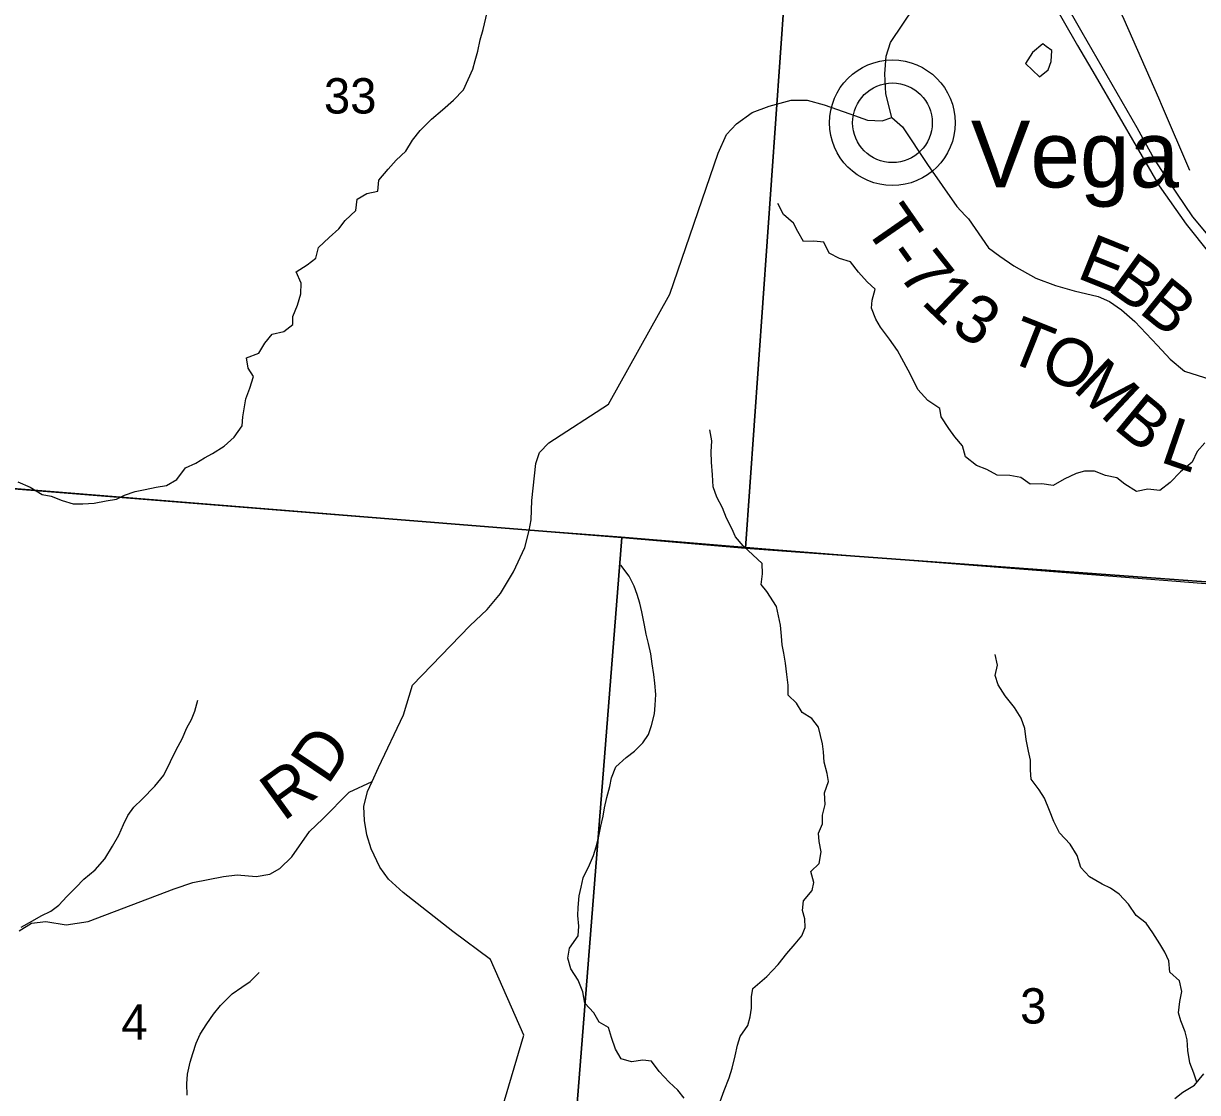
# Model space of a CAD drawing. Extents: x 0 to 42, y 0 to 22.
# Drawn here: x 6.349 to 7.044, y 16.803 to 17.436 of the extents above; entities that cross this region are included whole.
import ezdxf

# ---------------------------------------------------------------- set-up
doc = ezdxf.new("R2010")
doc.units = 0
for name, color, linetype in [('GM_X_Minor_Lake', 7, 'Continuous'), ('GM_X_Minor_River', 7, 'Continuous'), ('GM_X_Section', 7, 'Continuous'), ('GM_X_Section_Text', 7, 'Continuous'), ('GM_X_Township', 7, 'Continuous'), ('GM_X_Township_Road', 7, 'Continuous'), ('GM_X_Township_Road_Text', 7, 'Continuous'), ('GM_X_Unincorporated', 7, 'Continuous'), ('GM_X_Unincorporated_Location', 7, 'Continuous'), ('GM_X_Unincorporated_Text', 7, 'Continuous'), ('GM_X_US_Route', 7, 'Continuous')]:
    doc.layers.add(name, color=color, linetype=linetype)

msp = doc.modelspace()

# ---------------------------------------------------------------- linework, layer by layer
at = {"layer": 'GM_X_Minor_Lake'}
for points in [[(6.95479, 17.42238), (6.95275, 17.42391), (6.9467, 17.41878), (6.94255, 17.41232)], [(6.94255, 17.41232), (6.95089, 17.40437), (6.95599, 17.40856), (6.95768, 17.41349), (6.95805, 17.41994), (6.95479, 17.42238)]]:
    msp.add_lwpolyline(points, dxfattribs=at)
at = {"layer": 'GM_X_Minor_River'}
for points in [[(6.60387, 17.39057), (6.60975, 17.39661), (6.61243, 17.40285), (6.61529, 17.4089), (6.61663, 17.41401), (6.61817, 17.41969), (6.61971, 17.42632), (6.62144, 17.43238), (6.62375, 17.4426)], [(6.34589, 17.1645), (6.35305, 17.16125), (6.36022, 17.15705), (6.3655, 17.15588), (6.3721, 17.15339), (6.37852, 17.15147), (6.38438, 17.15144), (6.391, 17.15179), (6.39818, 17.15327), (6.40423, 17.15419), (6.40897, 17.15663), (6.4154, 17.15869), (6.42127, 17.15999), (6.4277, 17.16129), (6.43394, 17.16221), (6.44, 17.16578), (6.44513, 17.17277), (6.45119, 17.17558), (6.45631, 17.17859), (6.46104, 17.18122), (6.46805, 17.18555), (6.47394, 17.19102), (6.47869, 17.19763), (6.47909, 17.20294), (6.48006, 17.20881), (6.48084, 17.21373), (6.48313, 17.21998), (6.48543, 17.22679), (6.48224, 17.23173), (6.48132, 17.23799), (6.48851, 17.24061), (6.49213, 17.24666), (6.4965, 17.25194), (6.50331, 17.25343), (6.50862, 17.25776), (6.50864, 17.2625), (6.5115, 17.26912), (6.51342, 17.27575), (6.51364, 17.28219), (6.51064, 17.28884), (6.51709, 17.29298), (6.52239, 17.29693), (6.52393, 17.30337), (6.5302, 17.30922), (6.53589, 17.31431), (6.53969, 17.31922), (6.54595, 17.32525), (6.54673, 17.33188), (6.55242, 17.33527), (6.55904, 17.33676), (6.55963, 17.3432), (6.56514, 17.34962), (6.56989, 17.35509), (6.57558, 17.36037), (6.57958, 17.3668), (6.58414, 17.37265), (6.59078, 17.37926), (6.59723, 17.38491), (6.60387, 17.39057)], [(7.0487, 17.1876), (7.04417, 17.18247), (7.04116, 17.17621), (7.03436, 17.17031), (7.02813, 17.16404), (7.02209, 17.15929), (7.0149, 17.16003), (7.00828, 17.15869), (7.00128, 17.16304), (6.99654, 17.16682), (6.98992, 17.16814), (6.98348, 17.17078), (6.97743, 17.17076), (6.97252, 17.16943), (6.96552, 17.166), (6.95891, 17.16238), (6.95229, 17.16332), (6.94529, 17.16311), (6.9398, 17.16709), (6.93318, 17.16821), (6.9258, 17.16838), (6.91974, 17.17179), (6.9135, 17.17405), (6.90706, 17.17935), (6.90534, 17.18579), (6.90061, 17.19109), (6.89719, 17.19602), (6.89264, 17.20302), (6.89187, 17.20795), (6.88468, 17.21268), (6.8788, 17.21912), (6.87596, 17.2248), (6.87311, 17.23067), (6.86931, 17.23749), (6.86666, 17.24223), (6.8621, 17.24905), (6.85661, 17.25605), (6.85395, 17.26079), (6.85129, 17.26742), (6.85185, 17.27217), (6.85354, 17.27862), (6.8488, 17.28297), (6.84368, 17.28865), (6.83894, 17.29471), (6.83232, 17.29678), (6.82626, 17.29999), (6.82322, 17.30644), (6.81717, 17.30699), (6.81112, 17.30679), (6.8077, 17.31285), (6.80524, 17.31778), (6.79917, 17.32289), (6.79595, 17.32933)], [(6.78934, 17.09958), (6.78593, 17.10357), (6.78672, 17.11001), (6.78656, 17.11607), (6.7811, 17.12121), (6.77545, 17.12654), (6.77075, 17.13187), (6.76869, 17.13681), (6.76551, 17.14289), (6.76308, 17.14896), (6.7597, 17.15542), (6.75765, 17.16149), (6.7573, 17.16851), (6.75658, 17.17609), (6.75642, 17.18216), (6.75682, 17.18879), (6.75572, 17.19524)], [(6.74039, 16.79927), (6.73663, 16.80402), (6.73155, 16.80878), (6.72553, 16.81506), (6.72102, 16.82114), (6.71592, 16.82173), (6.70931, 16.82082), (6.70308, 16.82255), (6.6997, 16.82825), (6.69746, 16.83527), (6.6956, 16.84115), (6.69013, 16.8444), (6.68694, 16.84991), (6.68168, 16.85562), (6.68038, 16.86225), (6.67758, 16.86928), (6.67326, 16.87593), (6.67159, 16.88219), (6.67256, 16.88825), (6.67769, 16.89542), (6.6781, 16.9013), (6.67737, 16.90755), (6.67758, 16.91229), (6.67817, 16.91911), (6.67952, 16.92441), (6.68068, 16.9299), (6.6843, 16.93746), (6.68678, 16.94313), (6.68832, 16.94824), (6.68966, 16.95354), (6.69102, 16.96055), (6.69236, 16.96641), (6.69333, 16.97134), (6.69468, 16.97739), (6.69641, 16.98402), (6.69737, 16.98913), (6.69986, 16.99556), (6.70612, 17.00122), (6.71105, 17.00499), (6.71598, 17.00989), (6.71922, 17.0148), (6.72113, 17.0201), (6.72286, 17.0271), (6.72326, 17.03222), (6.72367, 17.03847), (6.72313, 17.0451), (6.7224, 17.05022), (6.72148, 17.05667), (6.72075, 17.06255), (6.71926, 17.06862), (6.71796, 17.07412), (6.71685, 17.07962), (6.71538, 17.0874), (6.71426, 17.09252), (6.71259, 17.09764), (6.71091, 17.10258), (6.70791, 17.10866), (6.70284, 17.11512)], [(6.78934, 16.87137), (6.79603, 16.87855), (6.80113, 16.88501), (6.80623, 16.89071), (6.81019, 16.89546), (6.81207, 16.90039), (6.81187, 16.90551), (6.81054, 16.91044), (6.81109, 16.91613), (6.81619, 16.92239), (6.81713, 16.92714), (6.81541, 16.93358), (6.82032, 16.93833), (6.82163, 16.94516), (6.8203, 16.95141), (6.81991, 16.95634), (6.82236, 16.96185), (6.82235, 16.96697), (6.82385, 16.97323), (6.82346, 16.98024), (6.8259, 16.98689), (6.82514, 16.99162), (6.82323, 16.99845), (6.82284, 17.00451), (6.82227, 17.00926), (6.81998, 17.01911), (6.816, 17.02422), (6.81032, 17.02782), (6.8069, 17.03331), (6.80198, 17.03804), (6.80197, 17.04392), (6.8012, 17.05036), (6.80043, 17.057), (6.79947, 17.06288), (6.79852, 17.0678), (6.79813, 17.07311), (6.79755, 17.07956), (6.79516, 17.09056), (6.78934, 17.09958)], [(7.04406, 16.80877), (7.04221, 16.8142), (7.03993, 16.82027), (7.03878, 16.82747), (7.0382, 16.83392), (7.03706, 16.83865), (7.03459, 16.8451), (7.03307, 16.84983), (7.034, 16.85666), (7.03512, 16.86254), (7.03379, 16.8688), (7.0281, 16.8739), (7.02734, 16.88073), (7.02506, 16.88584), (7.02202, 16.89077), (7.01804, 16.89721), (7.01405, 16.90289), (7.00799, 16.90761), (7.00363, 16.91424), (6.99795, 16.92011), (6.99283, 16.9237), (6.98791, 16.92616), (6.98053, 16.9305), (6.97541, 16.93599), (6.97313, 16.943), (6.96895, 16.94982), (6.9627, 16.95644), (6.95928, 16.96326), (6.95681, 16.96971), (6.95377, 16.9771), (6.95055, 16.98202), (6.94581, 16.98827), (6.94561, 16.99358), (6.9456, 16.99964), (6.94427, 17.00495), (6.94293, 17.01178), (6.94216, 17.01841), (6.94007, 17.02447), (6.93608, 17.03072), (6.93059, 17.03773), (6.92641, 17.04417), (6.92451, 17.04967), (6.92601, 17.05593), (6.92468, 17.06218)], [(6.34777, 16.90071), (6.35459, 16.90428), (6.3597, 16.90729), (6.36538, 16.9101), (6.37012, 16.91368), (6.37487, 16.91878), (6.38018, 16.92406), (6.38493, 16.92915), (6.39157, 16.93462), (6.39726, 16.94104), (6.40183, 16.94859), (6.40564, 16.95521), (6.4085, 16.96145), (6.41098, 16.96674), (6.41459, 16.97165), (6.41953, 16.97637), (6.42693, 16.9841), (6.43225, 16.99071), (6.43625, 16.99884), (6.43968, 17.00565), (6.44311, 17.01227), (6.44598, 17.0187), (6.44864, 17.02361), (6.45056, 17.02853), (6.45247, 17.03515)], [(6.44617, 16.80117), (6.44601, 16.8078), (6.44622, 16.81348), (6.44795, 16.82068), (6.44949, 16.82578), (6.4514, 16.83184), (6.45388, 16.83732), (6.45769, 16.84337), (6.46168, 16.84903), (6.46586, 16.85413), (6.4727, 16.86111), (6.47857, 16.86506), (6.4835, 16.86845), (6.48881, 16.87373)], [(6.76097, 16.7952), (6.76403, 16.8039), (6.76709, 16.81127), (6.76882, 16.81714), (6.77055, 16.82433), (6.77209, 16.83076), (6.77362, 16.83587), (6.77819, 16.8423), (6.77953, 16.84759), (6.78031, 16.85271), (6.78034, 16.85934), (6.78112, 16.86426), (6.78934, 16.87137)], [(7.03089, 16.7992), (7.0358, 16.80282), (7.0426, 16.807), (7.04807, 16.81365)]]:
    msp.add_lwpolyline(points, dxfattribs=at)
at = {"layer": 'GM_X_Section'}
for points in [[(6.30791, 17.67054), (6.81263, 17.63399), (6.77676, 17.12507), (6.70346, 17.13156), (6.27444, 17.16575)], [(6.81263, 17.63399), (7.32108, 17.59666), (7.2811, 17.08822), (7.23033, 17.09197), (6.77676, 17.12507)], [(6.27444, 17.16575), (6.70346, 17.13156), (6.66411, 16.63113), (6.13279, 16.66538), (6.17708, 17.17339)], [(6.70346, 17.13156), (6.77676, 17.12507), (7.23033, 17.09197), (7.19243, 16.58845), (6.66411, 16.63113)]]:
    msp.add_lwpolyline(points, close=True, dxfattribs=at)
at = {"layer": 'GM_X_Township'}
msp.add_lwpolyline([(8.42127, 18.51405), (8.38769, 18.10646), (8.32232, 17.47301), (8.30468, 17.09885), (8.29856, 17.02621), (8.2967, 17.00562), (8.09356, 17.02392), (8.06488, 17.0255), (8.03278, 17.02883), (7.97896, 17.0312), (7.36254, 17.08083), (7.35717, 17.08127), (7.35122, 17.08175), (7.35051, 17.0818), (7.34212, 17.08248), (7.2769, 17.08773), (7.22466, 17.09014), (6.78886, 17.12464), (6.70312, 17.1317), (6.64854, 17.1358), (6.05163, 17.18401)], dxfattribs=at)
at = {"layer": 'GM_X_Township_Road'}
msp.add_line((7.03992, 17.34894), (7.02376, 17.38659), dxfattribs=at)
for points in [[(7.02376, 17.38659), (7.02154, 17.39177), (7.00097, 17.43847), (6.9651, 17.51061), (6.94304, 17.55542), (6.92913, 17.58374), (6.9181, 17.60342), (6.90369, 17.62011), (6.89018, 17.63243), (6.8563, 17.65767), (6.85461, 17.66456), (6.85599, 17.66658)], [(6.86345, 17.38028), (6.85992, 17.39435), (6.85917, 17.40611), (6.86, 17.41672), (6.86255, 17.4247), (6.87678, 17.44592), (6.88007, 17.45636), (6.87859, 17.49329), (6.87184, 17.50777), (6.85399, 17.53713), (6.84322, 17.55482), (6.83976, 17.56263), (6.83919, 17.56995), (6.83977, 17.57614), (6.84534, 17.60408)], [(6.62664, 17.09231), (6.63157, 17.09831), (6.6394, 17.1112), (6.64604, 17.12559), (6.64865, 17.13554), (6.64976, 17.14204), (6.65016, 17.15343), (6.65261, 17.17542), (6.65467, 17.1819), (6.66036, 17.1876), (6.69569, 17.21052), (6.7319, 17.27562), (6.76056, 17.35915), (6.76558, 17.37017), (6.7715, 17.37658), (6.78071, 17.38333), (6.79083, 17.38711), (6.80374, 17.39057), (6.81328, 17.39057), (6.8234, 17.38777), (6.83844, 17.38247), (6.84906, 17.37873), (6.85761, 17.37831), (6.86345, 17.38028)], [(6.86345, 17.38028), (6.8697, 17.37477), (6.88459, 17.3524), (6.90186, 17.32756), (6.90686, 17.32233)], [(6.90686, 17.32233), (6.90885, 17.32024), (6.9207, 17.30314), (6.92744, 17.29812), (6.93558, 17.29236), (6.94858, 17.28512), (6.96026, 17.28076), (6.97136, 17.27764), (6.98567, 17.27435), (6.99233, 17.27139), (6.99949, 17.26645), (7.0073, 17.25938), (7.02071, 17.24531), (7.0282, 17.23717), (7.03675, 17.2301), (7.05221, 17.22508)], [(8.17227, 15.49063), (8.24231, 16.32059), (8.26133, 16.54947), (8.2967, 17.00562), (8.09356, 17.02392), (8.06488, 17.0255), (8.03278, 17.02883), (7.97896, 17.0312), (7.36254, 17.08083), (7.35717, 17.08127), (7.35122, 17.08175), (7.35051, 17.0818), (7.34212, 17.08248), (7.2769, 17.08773), (7.22466, 17.09014), (6.78886, 17.12464), (6.70312, 17.1317), (6.64854, 17.1358), (6.05163, 17.18401)], [(6.3467, 16.89845), (6.35393, 16.90294), (6.3624, 16.90393), (6.37449, 16.90206), (6.38745, 16.90406), (6.43842, 16.92325), (6.44951, 16.92699), (6.46771, 16.93073), (6.47578, 16.93164), (6.48704, 16.93071), (6.49516, 16.932), (6.50107, 16.93533), (6.50808, 16.94234), (6.5186, 16.95729), (6.52654, 16.96486), (6.54204, 16.98054), (6.55567, 16.98695), (6.55939, 16.99512), (6.57415, 17.0265), (6.57947, 17.0439), (6.61354, 17.07924), (6.62382, 17.08889), (6.62664, 17.09231)], [(6.63237, 16.79252), (6.64547, 16.83656), (6.62583, 16.88144), (6.6035, 16.89805), (6.57397, 16.92112), (6.56529, 16.92905), (6.56013, 16.93625), (6.55514, 16.94695), (6.55256, 16.95526), (6.55108, 16.96375), (6.55071, 16.97205), (6.55293, 16.98091), (6.55567, 16.98695)]]:
    msp.add_lwpolyline(points, dxfattribs=at)
at = {"layer": 'GM_X_Unincorporated'}
for radius in [0.0372, 0.02358]:
    msp.add_circle((6.86374, 17.37719), radius, dxfattribs=at)
at = {"layer": 'GM_X_Unincorporated_Location'}
msp.add_line((6.86374, 17.37719), (6.86374, 17.37719), dxfattribs=at)
at = {"layer": 'GM_X_US_Route'}
for points in [[(6.95715, 17.45149), (6.97335, 17.42297), (6.98388, 17.40518), (7.00942, 17.36087), (7.02174, 17.3398), (7.03773, 17.31705), (7.05174, 17.2995)], [(6.96162, 17.45586), (6.97583, 17.43092), (7.00852, 17.37448), (7.01872, 17.35571), (7.0275, 17.34229), (7.04153, 17.32149), (7.05353, 17.30711)]]:
    msp.add_lwpolyline(points, dxfattribs=at)

# ---------------------------------------------------------------- texts
at = {"layer": 'GM_X_Section_Text'}
for s, height, p in [('33', 0.020928, (6.52709, 17.38268)), ('3', 0.02093, (6.93938, 16.84351)), ('4', 0.02093, (6.40709, 16.83388))]:
    msp.add_text(s, height=height, rotation=0.00001, dxfattribs=at).set_placement(p)
at = {"layer": 'GM_X_Township_Road_Text'}
for s, rotation, p in [('T', 304.77295, (6.84635, 17.31582)), ('E', 338.10707, (6.97219, 17.28558)), ('-', 305.5713, (6.85872, 17.29801)), ('7', 308.38845, (6.86642, 17.28731)), ('B', 324.3979, (6.99033, 17.27852)), ('1', 316.24446, (6.88014, 17.27045)), ('B', 321.11894, (7.00896, 17.2652)), ('3', 327.23548, (6.89744, 17.25468)), ('T', 338.3108, (6.9301, 17.23674)), ('O', 333.39422, (6.94926, 17.22915)), ('M', 316.79011, (6.96983, 17.21919)), ('B', 320.56642, (6.99384, 17.19673)), ('L', 340.97641, (7.02146, 17.17654)), ('D', 55.97105, (6.52934, 16.98419)), ('R', 35.87614, (6.50302, 16.96287))]:
    msp.add_text(s, height=0.02841, rotation=rotation, dxfattribs=at).set_placement(p)
at = {"layer": 'GM_X_Unincorporated_Text'}
msp.add_text('Vega', height=0.039489, rotation=0.00001, dxfattribs=at).set_placement((6.91022, 17.33888))

doc.saveas('drawing.dxf')
